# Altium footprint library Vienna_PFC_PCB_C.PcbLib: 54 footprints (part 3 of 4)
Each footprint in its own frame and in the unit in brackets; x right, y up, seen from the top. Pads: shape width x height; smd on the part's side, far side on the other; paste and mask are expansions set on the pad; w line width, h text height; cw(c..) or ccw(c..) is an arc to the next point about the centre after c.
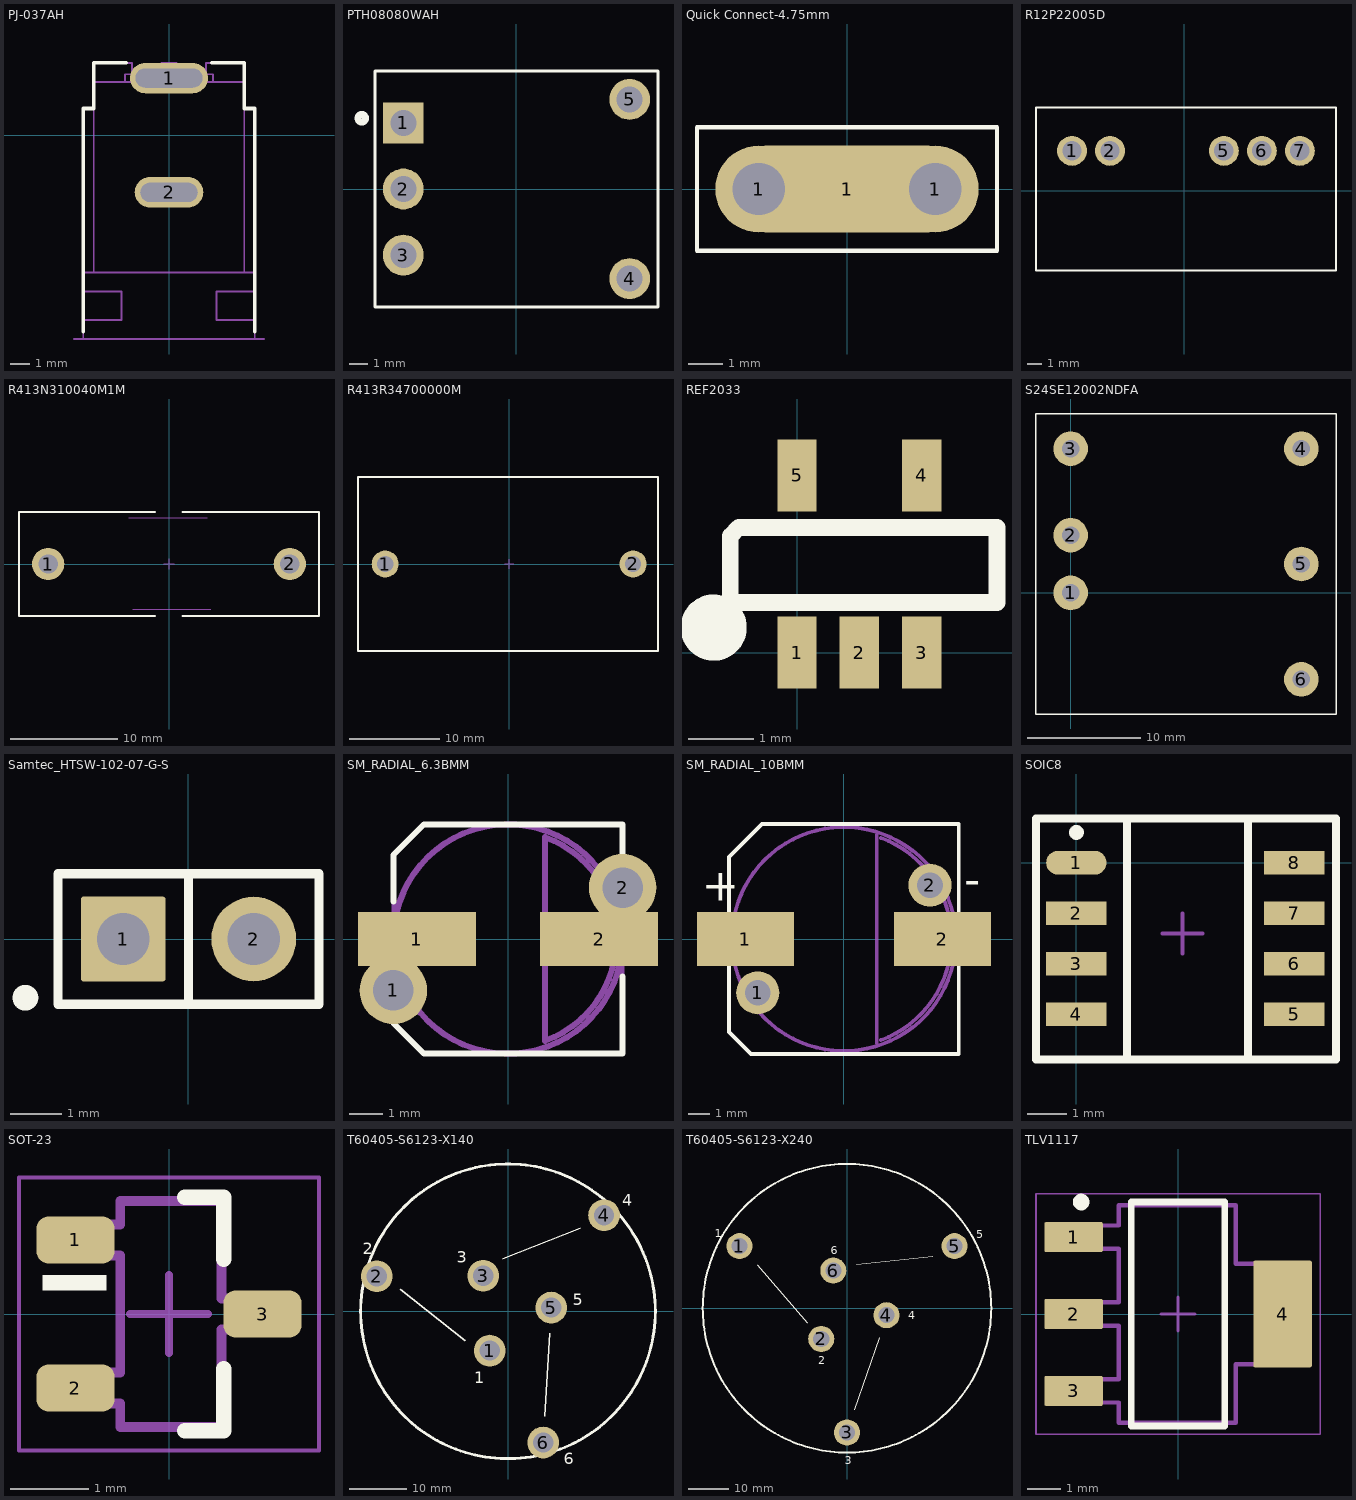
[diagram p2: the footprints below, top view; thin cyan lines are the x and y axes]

## PJ-037AH [mm] "Power Jack, 2mm, R/A, TH"
height 11.2
pads (2):
  oval 4.1x1.6 hole 1 slot 3.5 at 0 deg: 1(0,3)
  oval 3.6x1.6 hole 1 slot 3 at 0 deg: 2(0,-3)
Top Overlay:
  lines w0.2: -4.5,-10.3 -4.5,-9.7 -4.5,-8.2 -4.5,-7.2 -4.5,1.4 -3.95,1.4 -3.95,2.8 -3.95,3.8 -2.25,3.8 ; 2.25,3.8 3.95,3.8 3.95,2.8 3.95,1.4 4.5,1.4 4.5,-7.2 4.5,-8.2 4.5,-9.7 4.5,-10.3
Mechanical 1:
  lines w0.1: -5,-10.7 5,-10.7
Mechanical 5:
  lines w0.1: -3.95,-7.2 -3.95,1.4 ; -2.3,2.8 -2.3,3.2 2.3,3.2 2.3,2.8 ; -1.95,3.2 -1.95,3.8 -3.95,3.8 -3.95,2.8 ; -1.5,3.2 cw(c-1.3,3.2) -1.3,3.4 1.3,3.4 cw(c1.3,3.2) 1.5,3.2 ; -0.4,3.4 -0.4,3.656 -0.4,3.8 0.4,3.8 0.4,3.656 0.4,3.4 ; 1.95,3.2 1.95,3.8 3.95,3.8 3.95,2.8 ; 3.95,-7.2 3.95,1.4 ; -4.5,-9.7 -4.2,-9.7 -2.5,-9.7 -2.5,-8.2 -4.2,-8.2 -4.5,-8.2 ; -4.5,-9.7 -4.5,-8.2 ; -4.5,-9.7 -4.5,-10.7 -4.2,-10.7 4.2,-10.7 4.5,-10.7 4.5,-9.7 ; -4.5,-8.2 -4.5,-7.2 ; -4.5,-7.2 -4.2,-7.2 4.2,-7.2 4.5,-7.2 ; -4.5,-7.2 -4.5,1.4 -3.95,1.4 ; -3.95,1.4 -3.95,2.8 ; -3.95,2.8 3.95,2.8 ; 3.95,1.4 3.95,2.8 ; 3.95,1.4 4.5,1.4 4.5,-7.2 ; 4.5,-9.7 4.2,-9.7 2.5,-9.7 2.5,-8.2 4.2,-8.2 4.5,-8.2 ; 4.5,-9.7 4.5,-8.2 ; 4.5,-8.2 4.5,-7.2
3D body "PJ-037AH.stp": height 11, standoff -3.5, extent -4.5,-10.7 4.5,3.8

## PTH08080WAH [mm]
height 8.179
pads (5):
  rect 2.2x2.2 hole 1.4: 1(-6.096,3.556)
  round 2.2 hole 1.4: 2(-6.096,0) 3(-6.096,-3.556) 4(6.096,-4.826) 5(6.096,4.826)
Top Overlay:
  circle w0.381: c-8.331,3.81 r0.203
  lines w0.178: -7.62,-6.35 -7.62,6.35 7.62,6.35 7.62,-6.35 -7.62,-6.35
Mechanical 5:
  lines w0.102: -7.62,-6.35 -7.62,6.35 7.62,6.35 7.62,-6.35 -7.62,-6.35
3D body: height 1.52, standoff -3.56, extent 5.59,4.319 6.602,5.333
3D body: height 1.52, standoff -3.56, extent 5.59,-5.333 6.602,-4.319
3D body: height 1.52, standoff -3.56, extent -6.6,3.049 -5.588,4.063
3D body: height 1.52, standoff -3.56, extent -6.6,-0.507 -5.588,0.507
3D body: height 1.52, standoff -3.56, extent -6.602,-4.063 -5.59,-3.049
3D body: height 8.18, standoff 0.25, extent -7.619,-6.349 7.619,6.349

## Quick Connect-4.75mm [mm] "Quick Connect-4.75mm"
height 8.7
pads (3):
  round 2.5 hole 1.5: 1(-2.54,0) 1(2.54,0)
  rrect50% 6x2.5 smd: 1(0,0)
Top Overlay:
  lines w0.127: -4.318,-1.778 -4.318,1.778 4.318,1.778 4.318,-1.778 -4.318,-1.778
3D body: height 9, standoff 0, extent -3.81,-1.27 3.81,1.27

## R12P22005D [mm]
height 12.5
pads (5):
  round 2 hole 1.3: 1(-7.498,2.68) 2(-4.958,2.68) 5(2.662,2.68) 6(5.202,2.68) 7(7.742,2.68)
Top Overlay:
  lines w0.127: -9.906,-5.334 10.16,-5.334 10.16,5.588 -9.906,5.588 -9.906,-5.334
3D body: height 12.5, standoff 0, extent -9.398,-4.826 9.652,5.08

## R413N310040M1M [mm] "Capacitor"
height 17
pads (2):
  round 3 hole 1.8: 1(-11.25,0) 2(11.25,0)
Top Overlay:
  lines w0.178: -1.319,-4.826 -13.97,-4.826 -13.97,4.826 -1.319,4.826 ; 1.27,-4.826 13.97,-4.826 13.97,4.826 1.27,4.826
Mechanical 15:
  lines w0.1: -3.744,4.318 3.556,4.318 ; -3.396,-4.212 3.904,-4.212 ; -0.5,0 0.5,0 ; 0,-0.5 0,0.5
3D body "R413N310040M1M.step": height 17.1, standoff -35, extent -13.462,-4.353 13.338,4.353

## R413R34700000M [mm] "Capacitor"
height 33
pads (2):
  round 3 hole 1.8: 1(-13.75,0) 2(13.75,0)
Top Overlay:
  lines w0.178: -16.764,-9.652 16.51,-9.652 16.51,9.652 -16.764,9.652 -16.764,-9.652
Mechanical 15:
  lines w0.1: -0.5,0 0.5,0 ; 0,-0.5 0,0.5
3D body "R413R34700000M.step": height 33.1, standoff -6, extent -16.129,-9.103 16.171,9.103

## REF2033 [mm]
pads (5):
  rect 0.6x1.1 smd: 1(0,0) 2(0.95,0) 3(1.9,0) 4(1.9,2.7) 5(0,2.7)
Top Overlay:
  circle w0.5: c-1.27,0.381 r0.254
  lines w0.254: -1.016,0.762 -1.016,1.778 -0.889,1.905 3.048,1.905 3.048,0.762 -1.016,0.762
3D body "DBV0005A.stp": height 1.09, standoff 0, extent -0.508,0 2.413,2.845

## S24SE12002NDFA [mil]
height 401.57
pads (6):
  round 120 hole 60: 1(0,0) 2(0,200) 3(0,500) 4(800,500) 5(800,100) 6(800,-300)
Top Overlay:
  lines w5: -120,-420 -120,620 920,620 920,-420 -120,-420
3D body: height 401.57, standoff 0, extent -120,-420 920,620

## Samtec_HTSW-102-07-G-S [mm] "Samtec 100mil, 1x2, 230 mil above insulator"
height 8.382
pads (2):
  rrect6% 1.65x1.65 hole 1.016: 1(-1.27,0)
  round 1.65 hole 1.016: 2(1.27,0)
Top Overlay:
  circle w0.25: c-3.173,-1.143 r0.125
  lines w0.178: 0,-1.27 0,1.27 ; -2.54,-1.27 -2.54,1.27 2.54,1.27 2.54,-1.27 -2.54,-1.27
Mechanical 5:
  lines w0.127: -2.54,-1.27 2.54,-1.27 2.54,1.27 -2.54,1.27 -2.54,-1.27
3D body: height 8.38, standoff -2.03, extent 0.953,-0.317 1.587,0.317
3D body: height 8.38, standoff -2.03, extent -1.587,-0.317 -0.953,0.317
3D body: height 2.54, standoff 0, extent -2.539,-1.269 2.539,1.269

## SM_RADIAL_6.3BMM [mm] "Nichicon 6.3x7.7"
height 8
pads (4):
  round 2 hole 1.2: 1(-3.4,-1.524) 2(3.4,1.524)
  rect 3.5x1.6 smd: 1(-2.7,0) 2(2.7,0)
Top Overlay:
  lines w0.178: -3.4,-1.122 -3.4,-2.493 -2.493,-3.4 3.4,-3.4 3.4,-1.112 ; -3.4,1.108 -3.4,2.493 -2.493,3.4 3.4,3.4 3.4,1.118
Mechanical 5:
  lines w0.127: -3.4,-2.493 -2.493,-3.4 3.4,-3.4 3.4,3.4 -2.493,3.4 -3.4,2.493 -3.4,-2.493
Mechanical 13:
  circle w0.178: c0,0 r3.4
  lines w0.178: 1.1,-3.022 ccw(c0,0) 1.1,3.022 1.1,-3.022
3D body: height 8, standoff 6, extent 1.1,-3.023 3.217,3.023
3D body: height 8, standoff 1, extent -3.399,-3.399 3.399,3.399
3D body: height 1, standoff 0, extent -3.401,-3.401 3.401,3.401

## SM_RADIAL_10BMM [mm] "Nichicon 10x10.5"
height 10.5
pads (4):
  rect 4.5x2.5 smd: 1(-4.572,0) 2(4.572,0)
  round 2 hole 1.2: 1(-4,-2.5) 2(4,2.5)
Top Overlay:
  lines w0.178: -5.334,-1.122 -5.334,-4.318 -4.318,-5.334 5.334,-5.334 5.334,-1.112 ; -5.334,1.108 -5.334,3.81 -3.81,5.334 5.334,5.334 5.334,1.118
  text "-" at 5.588,2.032 h1.52
  text "+" at -6.604,1.778 h1.52
Mechanical 5:
  lines w0.127: -5.334,-4.318 -4.318,-5.334 5.334,-5.334 5.334,5.334 -3.81,5.334 -5.334,3.81 -5.334,-4.318
Mechanical 13:
  circle w0.178: c0,0 r5.2
  lines w0.178: 1.524,4.826 1.526,-4.826 ; 1.71,-4.698 ccw(c0,0) 1.71,4.698
3D body: height 1, standoff 0, extent -5.386,-5.334 5.386,5.334
3D body: height 10.5, standoff 6, extent 1.524,-5.08 4.942,4.826
3D body: height 10.5, standoff 1, extent -5.088,-5.121 4.902,5.088

## SOIC8 [mm]
height 1
pads (8):
  oval 1.52x0.6 smd: 1(0,0)
  rect 1.52x0.6 smd: 2(0,-1.27) 3(0,-2.54) 4(0,-3.81) 5(5.48,-3.81) 6(5.48,-2.54) 7(5.48,-1.27) 8(5.48,0)
Top Overlay:
  circle w0.3: c0,0.762 r0.036
  lines w0.2: -1.016,-4.953 6.528,-4.953 6.528,1.118 -1.016,1.118 -1.016,-4.953 ; 1.267,-4.953 4.318,-4.953 4.318,1.118 1.267,1.118 1.267,-4.953
Mechanical 13:
  lines w0.1: 1.267,-4.953 4.318,-4.953 4.318,1.118 1.267,1.118 1.267,-4.953
Mechanical 15:
  lines w0.1: 2.167,-1.778 3.167,-1.778 ; 2.667,-2.278 2.667,-1.278
3D body: height 1.7, standoff 0, extent 1.267,-4.826 4.318,1.016

## SOT-23 [mm] "SOT23, 3-Leads, Body 2.9x1.3mm, Pitch 0.95mm, Lead Span 2.5mm, IPC Medium Density"
height 1.1
pads (3):
  rrect50% 1x0.6 smd: 1(-1.2,0.95) 2(-1.2,-0.95) 3(1.2,0)
Top Overlay:
  rectangle: -1.625,0.3 -0.8,0.5
  lines w0.2: 0.2,-1.5 0.7,-1.5 0.7,-0.7 ; 0.2,1.5 0.7,1.5 0.7,0.7
Mechanical 5:
  lines w0.127: -1.16,-1.15 -0.625,-1.15 -0.625,-1.45 0.675,-1.45 0.675,-0.2 1.21,-0.2 1.21,0.2 0.675,0.2 0.675,1.45 -0.625,1.45 -0.625,1.15 -1.16,1.15 -1.16,0.75 -0.625,0.75 -0.625,-0.75 -1.16,-0.75 -1.16,-1.15
Mechanical 15:
  lines w0.05: -1.925,-1.75 -1.925,1.75 1.925,1.75 1.925,-1.75 -1.925,-1.75
  lines w0.1: -0.5,0 0.5,0 ; 0,-0.5 0,0.5
3D body "SW3dPS-sot-3p290x130ll237h100.STEP": height 1, standoff 0, extent -1.16,-1.45 1.21,1.45

## T60405-S6123-X140 [mm] "Common mode choke"
height 33
pads (6):
  round 5.5 hole 3.5: 1(-3.17,-6.797) 2(-22.699,6.082) 3(-4.302,6.144) 4(16.617,16.617) 5(7.471,0.654) 6(6.082,-22.699)
Top Overlay:
  circle w0.5: c0,0 r25.5
  lines w0.254: -18.625,3.866 -7.366,-5.08 ; -0.868,9.126 12.509,14.404 ; 6.328,-18.16 7.199,-3.805
  text "1" at -5.842,-12.446 h2
  text "5" at 11.176,1.016 h2
  text "3" at -8.89,8.382 h2
  text "6" at 9.652,-26.416 h2
  text "4" at 19.812,18.288 h2
  text "2" at -25.146,9.906 h2
3D body "6123-X140 3D Model.stp": height 32, standoff -5.5, extent -25.905,-26.164 26.092,25.834

## T60405-S6123-X240 [mm] "Common mode choke"
height 37
pads (6):
  round 6.5 hole 4: 1(-26.847,15.5) 2(-6.428,-7.66) 3(0,-31) 4(9.848,-1.736) 5(26.847,15.5) 6(-3.42,9.397)
Top Overlay:
  circle w0.5: c0,0 r36
  lines w0.254: -22.339,10.815 -9.906,-3.556 ; 1.899,-25.319 8.128,-7.366 ; 2.432,11.012 21.336,12.954
  text "1" at -33.02,17.78 h2
  text "5" at 32.258,17.526 h2
  text "3" at -0.508,-38.862 h2
  text "6" at -4.064,13.462 h2
  text "4" at 15.24,-2.794 h2
  text "2" at -7.112,-13.97 h2
3D body "T60405-S6123-X240.stp": height 36, standoff -5.5, extent -34.967,-34.967 34.917,34.901

## TLV1117 [mm] "SOT223/SC73, 4-Leads, Body 6.5x3.5mm, Pitch 2.3mm, Lead Span 7mm, IPC Medium Density"
height 1.8
pads (4):
  rrect11% 1.75x0.9 smd: 1(-3.125,2.3) 2(-3.125,0) 3(-3.125,-2.3)
  rrect6% 1.75x3.2 smd: 4(3.125,0)
Top Overlay:
  circle w0.25: c-2.9,3.35 r0.125
  lines w0.2: -1.4,-3.35 -1.4,3.35 1.4,3.35 1.4,-3.35 -1.4,-3.35
Mechanical 5:
  lines w0.127: -3.525,-2.65 -3.525,-1.95 -2.797,-1.95 -2.612,-1.95 -2.374,-1.95 -2.003,-1.95 -1.775,-1.95 -1.775,-0.35 -2.003,-0.35 -2.374,-0.35 -2.612,-0.35 -2.797,-0.35 -3.525,-0.35 -3.525,0.35 -2.797,0.35 -2.612,0.35 -2.374,0.35 -2.003,0.35 -1.775,0.35 -1.775,1.95 -2.003,1.95 -2.374,1.95 -2.612,1.95 -2.797,1.95 -3.525,1.95 -3.525,2.65 -2.797,2.65 -2.612,2.65 -2.374,2.65 -2.003,2.65 -1.775,2.65 -1.775,3.25 1.725,3.25 1.725,1.5 1.953,1.5 2.324,1.5 2.562,1.5 2.747,1.5 3.475,1.5 3.475,-1.5 2.747,-1.5 2.562,-1.5 2.324,-1.5 1.953,-1.5 1.725,-1.5 1.725,-3.25 -1.775,-3.25 -1.775,-2.65 -2.003,-2.65 -2.374,-2.65 -2.612,-2.65 -2.797,-2.65 -3.525,-2.65
Mechanical 15:
  lines w0.05: -4.25,-3.6 4.25,-3.6 4.25,3.6 -4.25,3.6 -4.25,-3.6
  lines w0.1: -0.5,0 0.5,0 ; 0,-0.5 0,0.5
3D body "DCY0004A.stp": height 1.68, standoff 0, extent -3.48,-3.25 3.48,3.25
